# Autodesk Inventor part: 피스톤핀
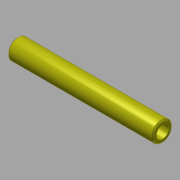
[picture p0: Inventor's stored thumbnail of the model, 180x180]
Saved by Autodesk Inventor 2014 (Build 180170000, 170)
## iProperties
Created: 2016-11
Part Number: 피스톤핀
Material: 강철, 탄소
Document SubType Name: Modeling
Designer: mduedu
Density: 7.87 g/cm^3
Mass: 13.9342 g
Surface Area: 24.1465 cm^2
Volume: 1.77055 cm^3
Appearance: 노란색
Author: mduedu
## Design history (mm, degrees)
sketch "스케치1"
  geometry: C1 r 2.5 at (0, 0); C2 r 4 at (0, 0); 1 further point
  constraints: 2 centre point, 2 coincident
  dimensions: "d0" = 5 diameter of C1; "d1" = 8 diameter of C2
extrude "돌출1" new body sketch "스케치1" stored distance "d2" = 58; taper "d3" = 0 deg
chamfer "모따기1" distance "d4" = 0.5; stored, may be unused: second distance "d5" = 2, angle "d6" = 45 deg
node "솔리드1"
